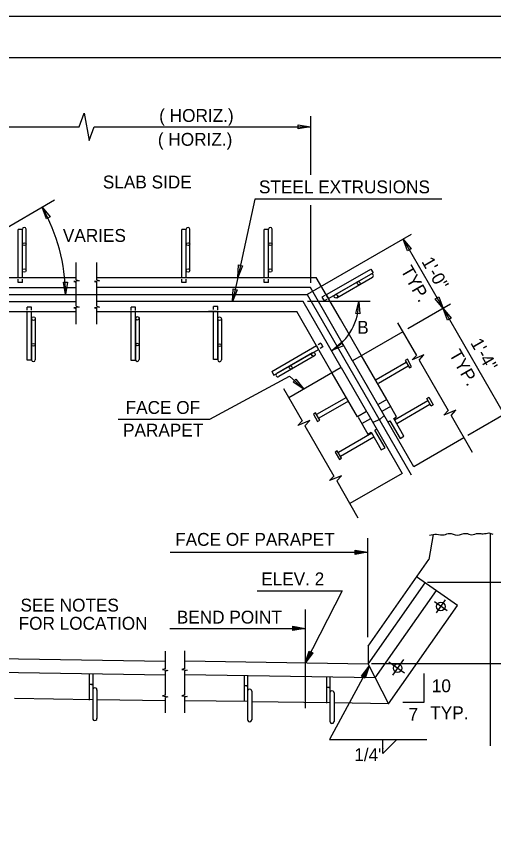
# Model space of a CAD drawing. Extents: x 0 to 22.7, y 0 to 15.7.
# Drawn here: x 7.73 to 11.6, y 8.07 to 14.67 of the extents above; entities that cross this region are included whole.
import ezdxf

# ---------------------------------------------------------------- set-up
doc = ezdxf.new("R2010")
doc.units = 0
for name, color, linetype in [('BORDER_ANNO_Cutsheet', 7, 'Continuous'), ('BRDG_ANNO_Anno-Sheet', 7, 'Continuous'), ('BRDG_ANNO_General-Notes', 7, 'Continuous'), ('BRDG_BASE_Dtlctrln', 7, 'Continuous'), ('BRDG_BASE_Hidden-Line', 7, 'Continuous'), ('BRDG_BASE_Obj-Line', 7, 'Continuous'), ('BRDG_BASE_Rebar', 7, 'Continuous')]:
    doc.layers.add(name, color=color, linetype=linetype)

msp = doc.modelspace()

# ---------------------------------------------------------------- linework, layer by layer
at = {"layer": 'BORDER_ANNO_Cutsheet'}
msp.add_lwpolyline([(0, 14.6667), (22.6667, 14.6667), (22.6667, 0), (0, 0)], close=True, dxfattribs=at)
at = {"layer": 'BRDG_ANNO_Anno-Sheet'}
msp.add_lwpolyline([(1, 14.3333), (22.3333, 14.3333), (22.3333, 0.3333), (1, 0.3333)], close=True, dxfattribs=at)
at = {"layer": 'BRDG_ANNO_General-Notes'}
for p, q in [((10.1113, 13.8591), (10.1113, 13.3828)), ((10.0113, 13.7554), (10.0113, 13.7887)), ((10.0113, 13.7887), (10.1113, 13.772)), ((5.3129, 13.772), (8.2374, 13.772)), ((8.3589, 13.772), (10.1113, 13.772)), ((10.1113, 13.772), (10.0113, 13.7554)), ((9.6603, 13.1865), (9.5233, 12.5529)), ((11.1762, 13.1865), (9.6603, 13.1865)), ((10.1113, 13.1383), (10.1113, 12.5071)), ((7.9735, 13.0259), (7.9379, 13.1208)), ((7.9379, 13.1208), (8.0023, 13.0426)), ((8.0023, 13.0426), (7.9735, 13.0259)), ((10.9286, 12.901), (10.0851, 12.414)), ((10.8628, 12.863), (11.1874, 12.3005)), ((10.8984, 12.7681), (10.8628, 12.863)), ((10.8628, 12.863), (10.9272, 12.7847)), ((10.9272, 12.7847), (10.8984, 12.7681)), ((9.5233, 12.5529), (9.5282, 12.6542)), ((9.5607, 12.6471), (9.5233, 12.5529)), ((9.5282, 12.6542), (9.5607, 12.6471)), ((9.5234, 12.5529), (9.4813, 12.3584)), ((8.1106, 12.514), (8.1439, 12.514)), ((8.1272, 12.414), (8.1106, 12.514)), ((8.1439, 12.514), (8.1272, 12.414)), ((9.4813, 12.3584), (9.4861, 12.4597)), ((9.5187, 12.4527), (9.4813, 12.3584)), ((9.4861, 12.4597), (9.5187, 12.4527)), ((10.5956, 12.3584), (10.0873, 12.3584)), ((10.4791, 12.2592), (10.5028, 12.3578)), ((10.5028, 12.3578), (10.5123, 12.2568)), ((11.2466, 12.3347), (10.9002, 12.1346)), ((11.123, 12.3788), (11.1519, 12.3955)), ((11.1874, 12.3005), (11.123, 12.3788)), ((11.1519, 12.3955), (11.1874, 12.3005)), ((11.1874, 12.3005), (11.6823, 11.4431)), ((11.223, 12.2056), (11.1874, 12.3005)), ((11.1874, 12.3005), (11.2519, 12.2222)), ((10.5123, 12.2568), (10.4791, 12.2592)), ((11.2519, 12.2222), (11.223, 12.2056)), ((10.2862, 11.9592), (10.3621, 12.0264)), ((10.3621, 12.0264), (10.3798, 11.9982)), ((10.3798, 11.9982), (10.2862, 11.9592)), ((9.2959, 11.4048), (9.9425, 11.7526)), ((9.9425, 11.7526), (10.0578, 11.6483)), ((9.9724, 11.703), (9.9948, 11.7277)), ((10.0578, 11.6483), (9.9724, 11.703)), ((9.9948, 11.7277), (10.0578, 11.6483)), ((11.7643, 11.4904), (11.3869, 11.2726)), ((8.5544, 11.4048), (9.2959, 11.4048)), ((10.578, 9.6391), (10.578, 10.4402)), ((8.9747, 10.3265), (10.573, 10.3265)), ((10.4758, 10.3396), (10.5427, 10.3286)), ((10.4758, 10.3358), (10.518, 10.3289)), ((10.4758, 10.3134), (10.5427, 10.3244)), ((10.4758, 10.3172), (10.518, 10.3241)), ((10.476, 10.3313), (10.5006, 10.3289)), ((10.476, 10.3217), (10.5006, 10.3241)), ((11.9091, 10.081), (11.0603, 10.081)), ((9.6816, 10.0148), (10.3686, 10.0148)), ((10.3686, 10.0148), (10.0705, 9.4295)), ((10.0705, 9.8621), (10.0705, 9.0652)), ((8.9727, 9.7106), (10.0705, 9.7106)), ((9.9732, 9.7237), (10.0401, 9.7127)), ((9.9732, 9.7199), (10.0155, 9.713)), ((9.9732, 9.6975), (10.0401, 9.7085)), ((9.9732, 9.7012), (10.0155, 9.7082)), ((9.9735, 9.7154), (9.9981, 9.713)), ((9.9735, 9.7058), (9.9981, 9.7082)), ((10.1029, 9.5221), (10.0824, 9.4575)), ((10.1263, 9.5102), (10.0861, 9.4556)), ((10.1063, 9.5204), (10.0933, 9.4796)), ((10.1229, 9.5119), (10.0976, 9.4774)), ((10.1102, 9.5181), (10.1012, 9.4951)), ((10.1188, 9.5137), (10.1055, 9.4929)), ((10.5884, 9.4044), (10.2675, 8.8111)), ((10.5306, 9.3251), (10.5722, 9.3787)), ((10.5537, 9.3127), (10.5758, 9.3767)), ((11.9191, 9.4241), (10.6057, 9.4241)), ((10.534, 9.3233), (10.5602, 9.3572)), ((10.5381, 9.3214), (10.5519, 9.3419)), ((10.5465, 9.3168), (10.5561, 9.3396)), ((10.5504, 9.3145), (10.5643, 9.3549)), ((11.0314, 9.3449), (11.0314, 9.111)), ((11.0314, 9.111), (10.8596, 9.111)), ((10.2675, 8.8111), (11.0542, 8.8111)), ((10.6979, 8.6986), (10.8106, 8.8111)), ((10.6979, 8.6986), (10.6979, 8.8111))]:
    msp.add_line(p, q, dxfattribs=at)
msp.add_lwpolyline([(8.2374, 13.772), (8.278, 13.8831), (8.3184, 13.6609), (8.3589, 13.772)], dxfattribs=at)
for points in [[(10.473, 10.343), (10.573, 10.3265), (10.473, 10.31)], [(9.9705, 9.7271), (10.0705, 9.7106), (9.9705, 9.6941)], [(10.1306, 9.5111), (10.0705, 9.4295), (10.1011, 9.5261)], [(10.5264, 9.3243), (10.5884, 9.4044), (10.5554, 9.3086)]]:
    msp.add_lwpolyline(points, close=True, dxfattribs=at)
for centre, radius, start, end in [((6.7133, 12.414), 1.4139, 360, 29.99372), ((10.0412, 12.3505), 0.4616, 302.04805, 0.90219)]:
    msp.add_arc(centre, radius, start, end, dxfattribs=at)
at = {"layer": 'BRDG_BASE_Dtlctrln'}
for p, q in [((6.4268, 12.2486), (8.039, 13.1792)), ((3.4358, 12.414), (10.0853, 12.414)), ((10.0853, 12.414), (10.9284, 10.9536)), ((11.2209, 9.8517), (11.116, 9.9251)), ((11.1326, 9.8361), (11.206, 9.941)), ((10.8746, 9.3481), (10.7482, 9.4366)), ((10.7791, 9.3312), (10.8676, 9.4576))]:
    msp.add_line(p, q, dxfattribs=at)
at = {"layer": 'BRDG_BASE_Hidden-Line'}
for p, q in [((10.8971, 11.8896), (10.879, 11.8792)), ((10.879, 11.8792), (10.9138, 11.819)), ((10.9318, 11.8294), (10.8971, 11.8896)), ((10.8878, 11.8641), (10.6451, 11.7241)), ((10.905, 11.834), (10.6629, 11.6942)), ((10.9138, 11.819), (10.9318, 11.8294)), ((10.4039, 11.5808), (10.1623, 11.4416)), ((10.421, 11.5506), (10.1797, 11.4116)), ((10.8104, 11.4232), (10.7325, 11.558)), ((10.7929, 11.4001), (11.0629, 11.5559)), ((11.0543, 11.571), (11.0724, 11.5814)), ((11.089, 11.5109), (11.0543, 11.571)), ((11.0724, 11.5814), (11.1071, 11.5212)), ((10.8109, 11.3704), (11.0804, 11.526)), ((11.1071, 11.5212), (11.089, 11.5109)), ((10.1536, 11.4567), (10.1355, 11.4462)), ((10.1355, 11.4462), (10.1703, 11.3861)), ((10.1884, 11.3966), (10.1536, 11.4567)), ((10.4973, 11.4195), (10.576, 11.2832)), ((10.7864, 11.4093), (10.8104, 11.4232)), ((10.8692, 11.2657), (10.7864, 11.4093)), ((10.1703, 11.3861), (10.1884, 11.3966)), ((10.7406, 11.3829), (10.7563, 11.392)), ((10.7563, 11.392), (10.8392, 11.2484)), ((10.6093, 11.2899), (10.3382, 11.1336)), ((10.576, 11.2832), (10.6034, 11.2991)), ((10.6034, 11.2991), (10.6862, 11.1556)), ((10.6335, 11.3165), (10.6485, 11.3252)), ((10.7164, 11.173), (10.6335, 11.3165)), ((10.6267, 11.2597), (10.3556, 11.1034)), ((10.8392, 11.2484), (10.8692, 11.2657)), ((10.3296, 11.1486), (10.3115, 11.1382)), ((10.3642, 11.0884), (10.3296, 11.1486)), ((10.6862, 11.1556), (10.7164, 11.173)), ((10.3115, 11.1382), (10.3461, 11.078)), ((10.3461, 11.078), (10.3642, 11.0884))]:
    msp.add_line(p, q, dxfattribs=at)
at = {"layer": 'BRDG_BASE_Obj-Line'}
for p, q in [((7.7785, 12.9405), (7.7437, 12.9405)), ((7.7437, 12.5527), (7.7437, 12.9405)), ((7.7785, 12.5527), (7.7785, 12.9405)), ((9.1053, 12.9405), (9.0706, 12.9405)), ((9.0706, 12.5527), (9.0706, 12.9405)), ((9.1053, 12.5527), (9.1053, 12.9405)), ((9.772, 12.9405), (9.7373, 12.9405)), ((9.7373, 12.5527), (9.7373, 12.9405)), ((9.772, 12.5527), (9.772, 12.9405)), ((8.2145, 12.5317), (8.2145, 12.6738)), ((8.3812, 12.5317), (8.3812, 12.6738)), ((10.2479, 12.4156), (10.6018, 12.62)), ((10.6018, 12.62), (10.6191, 12.5898)), ((5.3129, 12.5529), (8.2145, 12.5529)), ((7.7437, 12.5099), (7.7437, 12.5384)), ((7.7785, 12.5099), (7.7785, 12.5384)), ((8.2145, 12.5317), (8.237, 12.5244)), ((8.3812, 12.5529), (10.1593, 12.5529)), ((8.3812, 12.5317), (8.4036, 12.5244)), ((9.0706, 12.5099), (9.0706, 12.5384)), ((9.1053, 12.5099), (9.1053, 12.5384)), ((9.7373, 12.5099), (9.7373, 12.5384)), ((9.772, 12.5099), (9.772, 12.5384)), ((10.3556, 12.2129), (10.1593, 12.5529)), ((10.2625, 12.384), (10.6191, 12.5898)), ((5.3129, 12.4696), (8.2145, 12.4696)), ((7.7785, 12.5099), (7.7437, 12.5099)), ((8.237, 12.5244), (8.1944, 12.5187)), ((8.1944, 12.5187), (8.2145, 12.513)), ((8.2145, 12.3185), (8.2145, 12.513)), ((8.4036, 12.5244), (8.361, 12.5187)), ((8.361, 12.5187), (8.3812, 12.513)), ((8.3812, 12.3185), (8.3812, 12.513)), ((10.1113, 12.4696), (8.3812, 12.4696)), ((9.1053, 12.5099), (9.0706, 12.5099)), ((9.772, 12.5099), (9.7373, 12.5099)), ((10.4534, 11.8767), (10.1113, 12.4696)), ((10.2274, 12.4047), (10.2045, 12.3915)), ((10.2406, 12.4123), (10.2579, 12.3821)), ((5.3129, 12.3584), (8.2145, 12.3584)), ((10.0517, 12.3584), (8.3812, 12.3584)), ((10.3604, 11.8234), (10.0517, 12.3584)), ((10.2045, 12.3915), (10.2218, 12.3614)), ((10.2448, 12.3745), (10.2218, 12.3614)), ((5.3129, 12.2751), (8.2145, 12.2751)), ((7.8527, 12.3115), (7.8179, 12.3115)), ((7.818, 12.2863), (7.8179, 12.3115)), ((7.8179, 11.8809), (7.8179, 12.2748)), ((7.8527, 12.2858), (7.8527, 12.3115)), ((7.8527, 11.8809), (7.8527, 12.2748)), ((8.237, 12.3112), (8.1944, 12.3056)), ((8.1944, 12.3056), (8.2145, 12.2998)), ((8.2145, 12.3185), (8.237, 12.3112)), ((8.2145, 12.1738), (8.2145, 12.2998)), ((8.4036, 12.3112), (8.361, 12.3056)), ((8.361, 12.3056), (8.3812, 12.2998)), ((8.3812, 12.3185), (8.4036, 12.3112)), ((8.3812, 12.1738), (8.3812, 12.2998)), ((8.3812, 12.2751), (10.0011, 12.2751)), ((8.6944, 12.3109), (8.6596, 12.3109)), ((8.6597, 12.2857), (8.6596, 12.3109)), ((8.6596, 11.8803), (8.6596, 12.2767)), ((8.6944, 12.2855), (8.6944, 12.3109)), ((8.6944, 11.8803), (8.6944, 12.2767)), ((9.3028, 12.2751), (9.2862, 12.2751)), ((9.3514, 12.2751), (9.2919, 12.2751)), ((9.3608, 12.317), (9.3261, 12.317)), ((9.3261, 12.2919), (9.3261, 12.317)), ((9.3261, 11.8865), (9.3261, 12.2748)), ((9.3608, 12.2883), (9.3608, 12.317)), ((9.3608, 11.8865), (9.3608, 12.2733)), ((10.2879, 11.778), (10.0011, 12.2751)), ((10.5239, 11.9214), (10.3556, 12.2129)), ((10.3986, 12.1385), (10.4159, 12.1084)), ((10.8179, 12.1855), (10.9703, 11.9212)), ((10.8604, 12.1117), (10.4534, 11.8767)), ((10.1961, 12.0204), (10.1732, 12.0072)), ((10.1961, 12.0204), (10.2135, 11.9903)), ((9.799, 11.7916), (10.1598, 12)), ((9.8164, 11.7615), (10.1772, 11.9698)), ((10.1598, 12), (10.1772, 11.9698)), ((10.2135, 11.9903), (10.1905, 11.9771)), ((7.8527, 11.8809), (7.8179, 11.8809)), ((8.6944, 11.8803), (8.6596, 11.8803)), ((9.3608, 11.8865), (9.3261, 11.8865)), ((10.9486, 11.0194), (10.4515, 11.8799)), ((10.7303, 11.5639), (10.5239, 11.9214)), ((11.0312, 11.9245), (10.9351, 11.8849)), ((10.9351, 11.8849), (10.9703, 11.9212)), ((10.9929, 11.882), (11.0312, 11.9245)), ((10.9929, 11.882), (11.2281, 11.4744)), ((10.3606, 11.8232), (9.9362, 11.5781)), ((10.3606, 11.8232), (10.5663, 11.4668)), ((9.799, 11.7916), (9.8164, 11.7615)), ((10.4931, 11.4225), (10.2879, 11.778)), ((10.5733, 11.6792), (10.5731, 11.6787)), ((9.8923, 11.6541), (10.0448, 11.3898)), ((10.7303, 11.5639), (10.6595, 11.523)), ((10.7612, 11.506), (10.6915, 11.4658)), ((11.2891, 11.4777), (11.1929, 11.4379)), ((11.2508, 11.4352), (11.2891, 11.4777)), ((10.5673, 11.4654), (10.4931, 11.4225)), ((10.5678, 11.4641), (10.8555, 10.9657)), ((10.7098, 11.4343), (10.6732, 11.4007)), ((11.1929, 11.4379), (11.2281, 11.4744)), ((11.2508, 11.4352), (11.4226, 11.1374)), ((10.1057, 11.3931), (10.0095, 11.3535)), ((10.0095, 11.3535), (10.0448, 11.3898)), ((10.0674, 11.3507), (10.1057, 11.3931)), ((10.0674, 11.3507), (10.3026, 10.943)), ((10.5998, 11.4082), (10.5259, 11.3659)), ((10.5988, 11.4079), (10.5881, 11.4018)), ((10.6732, 11.4007), (10.6178, 11.3788)), ((10.6034, 11.2991), (10.6031, 11.2989)), ((11.3552, 11.2542), (10.9486, 11.0194)), ((10.8555, 10.9657), (10.4309, 10.7206)), ((10.3635, 10.9463), (10.2673, 10.9066)), ((10.2673, 10.9066), (10.3026, 10.943)), ((10.3253, 10.9039), (10.3635, 10.9463)), ((10.3253, 10.9039), (10.497, 10.606)), ((11.1058, 10.4697), (11.0716, 10.2694)), ((11.5709, 8.7603), (11.5709, 10.4743)), ((10.5789, 9.5658), (11.0716, 10.2694)), ((11.3021, 9.8965), (10.9722, 10.1276)), ((10.5796, 9.4217), (11.0404, 10.0797)), ((10.6368, 9.3096), (11.1326, 10.0177)), ((10.7441, 9.0996), (11.3021, 9.8965)), ((11.169, 9.888), (11.169, 9.888)), ((10.5789, 9.5658), (10.5789, 9.4217)), ((8.9369, 9.3836), (8.9369, 9.5257)), ((9.0935, 9.3858), (9.0935, 9.5279)), ((8.9369, 9.4424), (6.7133, 9.4766)), ((10.5796, 9.4217), (9.0935, 9.4445)), ((8.9369, 9.3312), (6.7133, 9.3654)), ((8.9369, 9.3836), (8.9144, 9.3764)), ((8.9144, 9.3764), (8.957, 9.3707)), ((8.957, 9.3707), (8.9369, 9.3649)), ((8.9369, 9.1705), (8.9369, 9.3649)), ((9.0935, 9.3858), (9.0711, 9.3785)), ((9.0711, 9.3785), (9.1137, 9.3729)), ((9.1137, 9.3729), (9.0935, 9.3671)), ((9.0935, 9.1726), (9.0935, 9.3671)), ((10.5796, 9.423), (10.5796, 9.4217)), ((10.5796, 9.4217), (10.7441, 9.0996)), ((8.3198, 9.3375), (8.3198, 9.1284)), ((8.3198, 9.3367), (8.3198, 9.2653)), ((8.3476, 9.3367), (8.3476, 9.1297)), ((10.6368, 9.3096), (9.0935, 9.3334)), ((9.5748, 9.3276), (9.5748, 9.1185)), ((9.5748, 9.3267), (9.5748, 9.2553)), ((9.6026, 9.3267), (9.6026, 9.1198)), ((10.2415, 9.3143), (10.2415, 9.1052)), ((10.2415, 9.3135), (10.2415, 9.242)), ((10.2693, 9.3135), (10.2693, 9.1065)), ((8.3469, 9.256), (8.3191, 9.256)), ((8.3382, 9.2559), (8.3469, 9.256)), ((9.6019, 9.246), (9.5741, 9.246)), ((9.5932, 9.2459), (9.6019, 9.246)), ((10.2685, 9.2328), (10.2408, 9.2328)), ((10.2598, 9.2327), (10.2685, 9.2328)), ((8.9369, 9.1705), (8.9144, 9.1632)), ((9.0935, 9.1726), (9.0711, 9.1653)), ((8.3473, 9.132), (7.7153, 9.1417)), ((8.9369, 9.123), (8.3821, 9.1315)), ((8.9144, 9.1632), (8.957, 9.1575)), ((8.957, 9.1575), (8.9369, 9.1517)), ((8.9369, 9.0257), (8.9369, 9.1517)), ((9.0711, 9.1653), (9.1137, 9.1596)), ((9.1137, 9.1596), (9.0935, 9.1539)), ((9.0935, 9.0279), (9.0935, 9.1539)), ((9.6027, 9.1172), (9.0935, 9.1249)), ((10.2689, 9.1069), (9.6384, 9.1166)), ((10.7441, 9.0996), (10.3037, 9.1064))]:
    msp.add_line(p, q, dxfattribs=at)
for centre in [(11.1692, 9.8879), (10.8184, 9.3874)]:
    msp.add_circle(centre, 0.0347, dxfattribs=at)
msp.add_spline([(11.0769, 10.4652), (11.134, 10.4723), (11.1945, 10.4688), (11.2373, 10.4795), (11.3014, 10.4652), (11.3727, 10.4795), (11.4155, 10.4688), (11.4724, 10.4795), (11.5117, 10.4759), (11.558, 10.483), (11.5901, 10.4723)], degree=3, dxfattribs=at)
at = {"layer": 'BRDG_BASE_Rebar'}
for p, q in [((7.7785, 12.6084), (7.7785, 12.9423)), ((7.8078, 12.6084), (7.8078, 12.9423)), ((9.1053, 12.6084), (9.1053, 12.9423)), ((9.1346, 12.6084), (9.1346, 12.9423)), ((9.772, 12.6084), (9.772, 12.9423)), ((9.8014, 12.6084), (9.8014, 12.9423)), ((10.3107, 12.4118), (10.5999, 12.5788)), ((10.3254, 12.3864), (10.6146, 12.5534)), ((7.8527, 12.2192), (7.8527, 11.8852)), ((7.882, 12.2192), (7.882, 11.8852)), ((8.6944, 12.221), (8.6944, 11.887)), ((8.7237, 12.221), (8.7237, 11.887)), ((9.3608, 12.2176), (9.3608, 11.8836)), ((9.3901, 12.2176), (9.3901, 11.8836)), ((10.129, 11.942), (9.84, 11.7747)), ((10.1437, 11.9166), (9.8546, 11.7493)), ((8.3823, 9.2129), (8.3823, 8.9809)), ((9.6373, 9.203), (9.6373, 8.9709)), ((10.304, 9.1897), (10.304, 8.9577)), ((8.3476, 9.1297), (8.3476, 8.9791)), ((9.6026, 9.1198), (9.6026, 8.9691)), ((10.2693, 9.1065), (10.2693, 8.9558))]:
    msp.add_line(p, q, dxfattribs=at)
for centre in [(7.7931, 12.6084), (9.12, 12.6084), (9.7867, 12.6084), (10.318, 12.3991), (7.8673, 12.2192), (8.709, 12.221), (9.3754, 12.2176), (10.1364, 11.9293)]:
    msp.add_circle(centre, 0.0146, dxfattribs=at)
for centre, radius, start, end in [((7.7931, 12.9424), 0.0146, 0, 180), ((9.12, 12.9424), 0.0146, 0, 180), ((9.7867, 12.9424), 0.0146, 0, 180), ((10.6072, 12.5661), 0.0146, 300.00693, 120.00693), ((7.8673, 11.8852), 0.0146, 180, 0), ((8.709, 11.887), 0.0146, 180, 0), ((9.3754, 11.8836), 0.0146, 180, 0), ((9.8473, 11.762), 0.0146, 120.06025, 300.06025), ((8.3649, 9.211), 0.0174, 359.88448, 181.2603), ((9.6199, 9.201), 0.0174, 359.88448, 181.2603), ((10.2866, 9.1878), 0.0174, 359.88448, 181.2603), ((8.3649, 8.9816), 0.0174, 173.10257, 2.63902), ((9.6199, 8.9716), 0.0174, 173.10257, 2.63902), ((10.2866, 8.9583), 0.0174, 173.10257, 2.63902)]:
    msp.add_arc(centre, radius, start, end, dxfattribs=at)
for centre, major_axis in [((7.7931, 12.8215), (0.0146, 0)), ((9.12, 12.8215), (0.0146, 0)), ((9.7867, 12.8215), (0.0146, 0)), ((10.5026, 12.5057), (0.0073, -0.0127)), ((7.8673, 12.006), (0.0146, 0)), ((8.709, 12.0079), (0.0146, 0)), ((9.3754, 12.0045), (0.0146, 0)), ((9.9519, 11.8225), (0.0073, -0.0127))]:
    msp.add_ellipse(centre, major_axis=major_axis, ratio=0.7425, dxfattribs=at)

# ---------------------------------------------------------------- texts
at = {"layer": 'BRDG_ANNO_General-Notes'}
for s, height, p in [('( HORIZ.)', 0.10417, (8.8864, 13.8115)), ('( HORIZ.)', 0.10417, (8.8757, 13.6181)), ('SLAB SIDE', 0.10417, (8.4299, 13.2726)), ('STEEL EXTRUSIONS', 0.104167, (9.6947, 13.2332)), ('VARIES', 0.10417, (8.1061, 12.8401)), ('B', 0.1042, (10.4907, 12.0963)), ('FACE OF', 0.10417, (8.6147, 11.4471)), ('PARAPET', 0.10417, (8.5938, 11.2634)), ('FACE OF PARAPET', 0.104167, (9.0158, 10.3789)), ('ELEV. 2', 0.10417, (9.7126, 10.059)), ('SEE NOTES', 0.10417, (7.7626, 9.8468)), ('BEND POINT', 0.10417, (9.0293, 9.7494)), ('FOR LOCATION', 0.104167, (7.7473, 9.6995)), ('10', 0.10417, (11.0952, 9.1935)), ('7', 0.1042, (10.907, 8.9627)), ('TYP.', 0.10417, (11.083, 8.9749)), ('1/4"', 0.10417, (10.4669, 8.6356))]:
    msp.add_text(s, height=height, dxfattribs=at).set_placement(p)
for s, rotation, p in [('1\'-0"', 299.99543, (11.0087, 12.6811)), ('TYP.', 299.99301, (10.8397, 12.6096)), ('1\'-4"', 299.99543, (11.4047, 12.0227)), ('TYP.', 299.99301, (11.2321, 11.9307))]:
    msp.add_text(s, height=0.10417, rotation=rotation, dxfattribs=at).set_placement(p)

doc.saveas('drawing.dxf')
